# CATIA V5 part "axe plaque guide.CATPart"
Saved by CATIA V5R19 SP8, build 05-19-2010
Part number: axe plaque guide
Revision: ANY
Definition: UNKNOWN
Nomenclature: axe plaque guide
Source: Unknown
Bounding box of the stored display mesh (mm): x 0 to 11, y -3 to 3, z -3 to 3
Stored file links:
  D:\Documents\1_Travail\1 - ac-limoges.fr\ac-limoges.fr\Emmanuel Maynard - STI2D_Turgot\2 -2I2D\2_SEQUENCE_Serrure_Biométrique\5-Spé_ITEC\Serrure_Bio_Eleve\axe plaque guide.CATPart
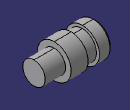
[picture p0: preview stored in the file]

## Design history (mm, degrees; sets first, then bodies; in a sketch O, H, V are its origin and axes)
Body1 "Chanfrein1" (main body)
  Solid1: solid without history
